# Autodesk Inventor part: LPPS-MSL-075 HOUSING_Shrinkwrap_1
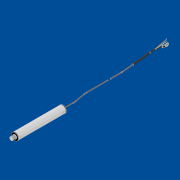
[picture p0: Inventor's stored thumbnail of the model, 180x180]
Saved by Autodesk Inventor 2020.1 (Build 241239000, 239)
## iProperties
Created: 2019-07
Part Number: LPPS-MSL-075 HOUSING_Shrinkwrap_1
Material: Generic
Document SubType Name: Modeling
Designer: J. Nielson
Density: 1 g/cm^3
Appearance: Default
Author: J. Nielson
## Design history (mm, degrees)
node "Assembly1"
body "Solid1"
node "Part1:1"
node "Part2:1"
body "Solid2"
node "Part3:1"
body "Solid3"
node "Part4:1"
body "Solid4"
node "Part5:1"
body "Solid5"
node "Part6:1"
body "Solid6"
node "Part7:1"
body "Solid7"
node "Part8:1"
body "Solid8"
node "Part9:1"
body "Solid9"
node "Part10:1"
body "Solid10"
node "Part11:1"
body "Solid11"
node "Part12:1"
body "Solid12"
node "Part13:1"
body "Solid13"
node "Part14:1"
body "Solid14"
node "Part15:1"
body "Solid15"
node "Part16:1"
body "Solid16"
node "Part17:1"
body "Solid17"
node "Part16:2"
body "Solid18"
node "Part17:2"
body "Solid19"
